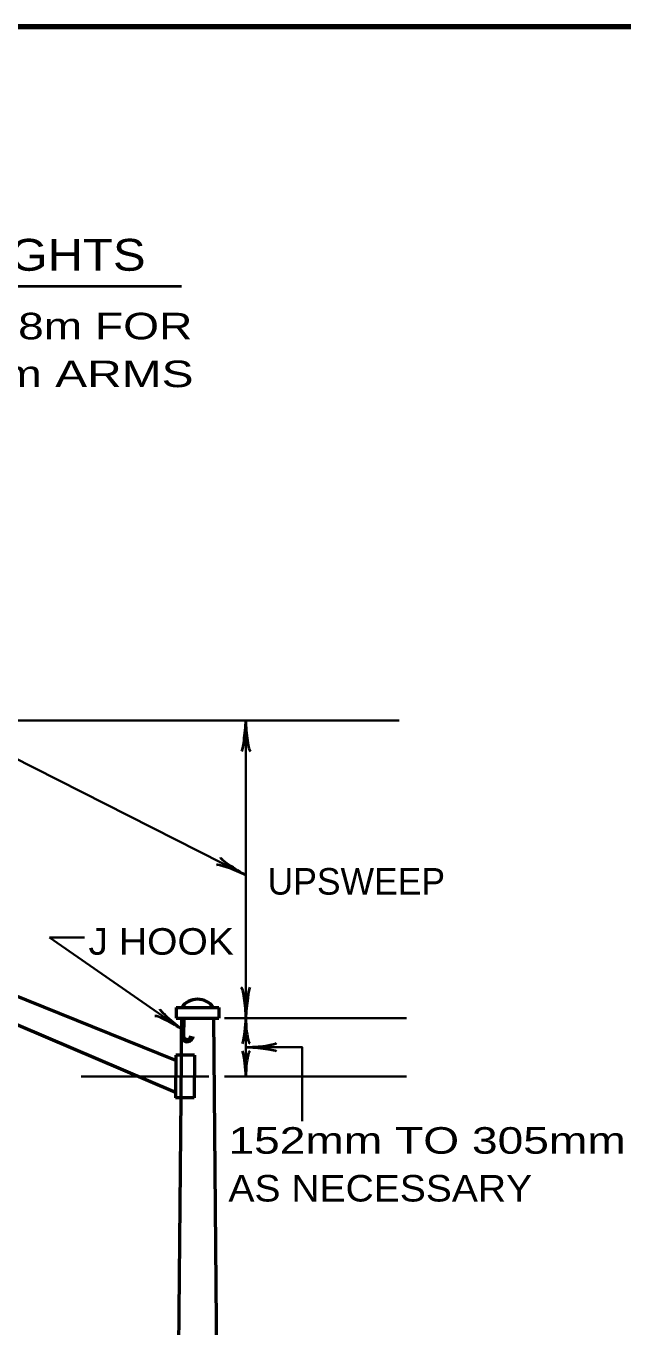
# Model space of a CAD drawing. Extents: x -23 to 690, y -228 to 443.
# Drawn here: x 173.2 to 229.5, y 315.3 to 437.8 of the extents above; entities that cross this region are included whole.
import ezdxf
from ezdxf.enums import TextEntityAlignment as Align

# ---------------------------------------------------------------- set-up
doc = ezdxf.new("R2010")
doc.units = 0
doc.layers.add('1', color=7, linetype='Continuous', lineweight=35)

msp = doc.modelspace()

# ---------------------------------------------------------------- linework, layer by layer
at = {"layer": '1', "lineweight": 40}
msp.add_line((86.751, 413.314), (187.874, 413.314), dxfattribs=at)
at = {"layer": '1'}
for p, q in [((98.393, 372.411), (208.393, 372.411)), ((193.945, 344.411), (193.945, 372.411)), ((175.442, 351.987), (178.75, 351.987)), ((175.442, 351.987), (187.982, 343.297)), ((191.945, 344.411), (209.091, 344.411)), ((193.945, 344.411), (193.945, 338.911)), ((178.445, 338.911), (190.445, 338.911)), ((191.945, 338.911), (209.091, 338.911))]:
    msp.add_line(p, q, dxfattribs=at)
at = {"layer": '1', "lineweight": 53}
for p, q in [((187.36, 340.411), (119.676, 367.757)), ((187.323, 337.411), (119.205, 366.325)), ((187.393, 345.411), (191.393, 345.411)), ((187.393, 345.411), (187.393, 344.411)), ((191.393, 345.411), (191.393, 344.411)), ((187.393, 344.411), (191.393, 344.411)), ((190.893, 344.411), (191.784, 249.412)), ((187.36, 340.911), (187.323, 336.911)), ((189.11, 340.911), (187.36, 340.911)), ((189.11, 340.911), (189.073, 336.911)), ((189.073, 336.911), (187.323, 336.911))]:
    msp.add_line(p, q, dxfattribs=at)
at = {"layer": '1', "lineweight": 90}
msp.add_line((187.993, 344.411), (187.976, 342.661), dxfattribs=at)
at = {"layer": '1', "lineweight": 158}
msp.add_lwpolyline([(684.026, 437.805), (24.276, 437.722), (24.36, -0.611)], dxfattribs=at)
at = {"layer": '1'}
for points in [[(193.935, 357.878), (138.687, 385.856), (130.502, 385.856)], [(193.945, 341.661), (199.26, 341.661), (199.26, 334.69)]]:
    msp.add_lwpolyline(points, dxfattribs=at)
at = {"layer": '1', "lineweight": 53}
msp.add_lwpolyline([(187.893, 344.411), (187.86, 340.911), (187.823, 336.911), (187.002, 249.412)], dxfattribs=at)
msp.add_arc((189.393, 344.363), 1.822, 35.09936, 144.90064, dxfattribs=at)
at = {"layer": '1', "lineweight": 90}
msp.add_arc((188.415, 342.719), 0.442, 187.53327, 0.04815, dxfattribs=at)
at = {"layer": '1', "lineweight": 40}
for centre, major_axis, ratio, start_param, end_param in [((193.733, 371.29), (0.176, 1.756), 0.07063, 3.1407148, 5.41811), ((194.221, 371.32), (-0.156, 1.786), 0.122415, 0.8963533, 3.1415927), ((192.836, 358.125), (1.664, -0.667), 0.122415, 0.8963533, 3.1415927), ((193.031, 358.573), (-1.488, 0.95), 0.07063, 6.2823074, 8.5597026), ((193.668, 345.502), (0.156, -1.786), 0.122415, 0.8963533, 3.1415927), ((194.156, 345.531), (-0.176, -1.756), 0.07063, 3.1407148, 5.41811), ((186.928, 343.691), (1.557, -0.889), 0.122415, 0.8963533, 3.1415927), ((187.182, 344.109), (-1.344, 1.145), 0.07063, 6.2823074, 8.5597026), ((193.736, 343.281), (0.176, 1.756), 0.07063, 4.6265008, 5.41811), ((194.224, 343.31), (-0.156, 1.786), 0.122415, 0.8963533, 1.6612166), ((193.794, 343.773), (0.176, 1.756), 0.07063, 3.1407148, 4.3375003), ((194.164, 343.82), (-0.156, 1.786), 0.122415, 1.9568509, 3.1415927), ((195.036, 341.937), (-1.786, -0.156), 0.122415, 0.8963533, 3.1415927), ((193.794, 339.549), (0.176, -1.756), 0.07063, 1.9456851, 3.1424706), ((195.065, 341.449), (-1.756, 0.176), 0.07063, 3.1407148, 5.41811), ((194.164, 339.502), (-0.156, -1.786), 0.122415, 3.1415927, 4.3263344), ((193.736, 340.041), (0.176, -1.756), 0.07063, 0.8650754, 1.6566845), ((194.224, 340.011), (-0.156, -1.786), 0.122415, 4.6219687, 5.386832)]:
    msp.add_ellipse(centre, major_axis=major_axis, ratio=ratio, start_param=start_param, end_param=end_param, dxfattribs=at)

# ---------------------------------------------------------------- texts
at = {"layer": '1'}
for s, height, width, p in [('9.1m THROUGH 15.2m MOUNTING HEIGHTS', 3, 1.15, (87.353, 414.765)), ('J HOOK', 2.5, 1.1, (179.125, 350.373)), ('152mm TO 305mm', 2.5, 1.3, (192.305, 331.638)), ('AS NECESSARY', 2.5, 1.1, (192.305, 327.138))]:
    msp.add_text(s, height=height, dxfattribs=dict(at, width=width)).set_placement(p)
for s, width, p in [('UPSWEEP 0.9m FOR 1.2m - 3.0m ARMS, 1.8m FOR', 1.3, (137.107, 408.307)), ('3.7m - 4.6m ARMS, 2.1m FOR 6.1m - 10.7m ARMS', 1.35, (137.107, 403.807))]:
    msp.add_text(s, height=2.5, dxfattribs=dict(at, width=width)).set_placement(p, align=Align.CENTER)
msp.add_text('UPSWEEP', height=2.5, dxfattribs=at).set_placement((195.995, 356.03))

doc.saveas('drawing.dxf')
